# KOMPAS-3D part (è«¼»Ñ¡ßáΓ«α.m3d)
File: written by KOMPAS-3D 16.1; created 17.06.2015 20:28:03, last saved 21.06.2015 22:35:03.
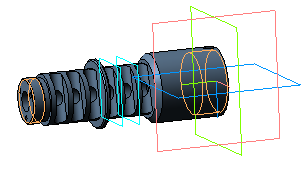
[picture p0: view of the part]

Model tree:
1. Эскиз:1
2. Операция выдавливания:1
     Расстояние 1 = 29
3. Эскиз:2
4. Вырезать элемент выдавливания:1
     Расстояние 1 = 10
5. Эскиз:3
6. Вырезать элемент выдавливания:2
     Расстояние 1 = 5
7. Эскиз:4
8. Вырезать элемент выдавливания:3
     Расстояние 1 = 12
9. Фаска:1
     Угол = 45; Длина 1 = 1; Длина 2 = 1
10. Фаска:2
     Угол = 45; Длина 1 = 2; Длина 2 = 2
11. Эскиз:5
12. Операция выдавливания:2
     Расстояние 1 = 19
13. Эскиз:12
14. Вырезать элемент выдавливания:6
     Расстояние 2 = 5; Расстояние 1 = 62
15. Смещенная плоскость:2
     Расстояние = 7
16. Эскиз:13
17. Вырезать элемент выдавливания:7
     Расстояние 2 = 5; Расстояние 1 = 62
18. Смещенная плоскость:3
     Расстояние = 14
19. Эскиз:14
20. Вырезать элемент выдавливания:8
     Расстояние 2 = 5; Расстояние 1 = 62
21. Эскиз:15
22. Операция выдавливания:7
     Расстояние 1 = 2
23. Эскиз:16
24. Операция выдавливания:8
     Расстояние 1 = 5
25. Эскиз:17
26. Вырезать элемент выдавливания:9
     Расстояние 2 = 5; Расстояние 1 = 5
27. Эскиз:18
28. Операция выдавливания:9
     Расстояние 1 = 7
29. Эскиз:19
30. Вырезать элемент выдавливания:10
     Расстояние 2 = 5; Расстояние 1 = 5
31. Эскиз:20
32. Операция выдавливания:10
     Расстояние 1 = 7
33. Эскиз:21
34. Вырезать элемент выдавливания:11
     Расстояние 2 = 5; Расстояние 1 = 5
35. Эскиз:22
36. Операция выдавливания:11
     Расстояние 1 = 2
37. Эскиз:23
38. Операция выдавливания:12
     Расстояние 1 = 2
39. Эскиз:24
40. Операция выдавливания:13
     Расстояние 1 = 5
41. Фаска:5
     Угол = 45; Длина 1 = 0.5; Длина 2 = 0.5
42. Фаска:6
     Угол = 45; Длина 1 = 0.5; Длина 2 = 0.5
43. Эскиз:25
44. Эскиз:26
45. Вырезать элемент выдавливания:13
     Расстояние 2 = 5; Расстояние 1 = 14
46. Эскиз:27
47. Вырезать элемент выдавливания:14
     Расстояние 2 = 15; Расстояние 1 = 14
48. Эскиз:28
49. Вырезать элемент выдавливания:15
     Расстояние 2 = 15; Расстояние 1 = 14
50. Условное изображение резьбы:1
     Длина резьбы = 10; Шаг резьбы = 1.5; Номинальный диаметр резьбы = 24.1238
51. Условное изображение резьбы:2
     Длина резьбы = 4; Шаг резьбы = 1; Номинальный диаметр резьбы = 18
52. Скругление:1
     Радиус = 2.5
53. Скругление:2
     Радиус = 2.5
54. Вырезать элемент выдавливания:16
     Расстояние 2 = 15; Расстояние 1 = 54
55. Массив по концентрической сетке:2  (with: Вырезать элемент выдавливания:13)  (labels: Zebra 002; Сталь 20 ГОСТ 1050-88; SYSTEM_PROPERTY_ADDITIONAL_FOR:9.000000; SYSTEM_PROPERTY_ADDITIONAL_FOR:20.000000)  (3 pattern instances)
     Шаг 2 = 360

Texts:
  Body Specification ( left align )
  Body Specificaton ( centered )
